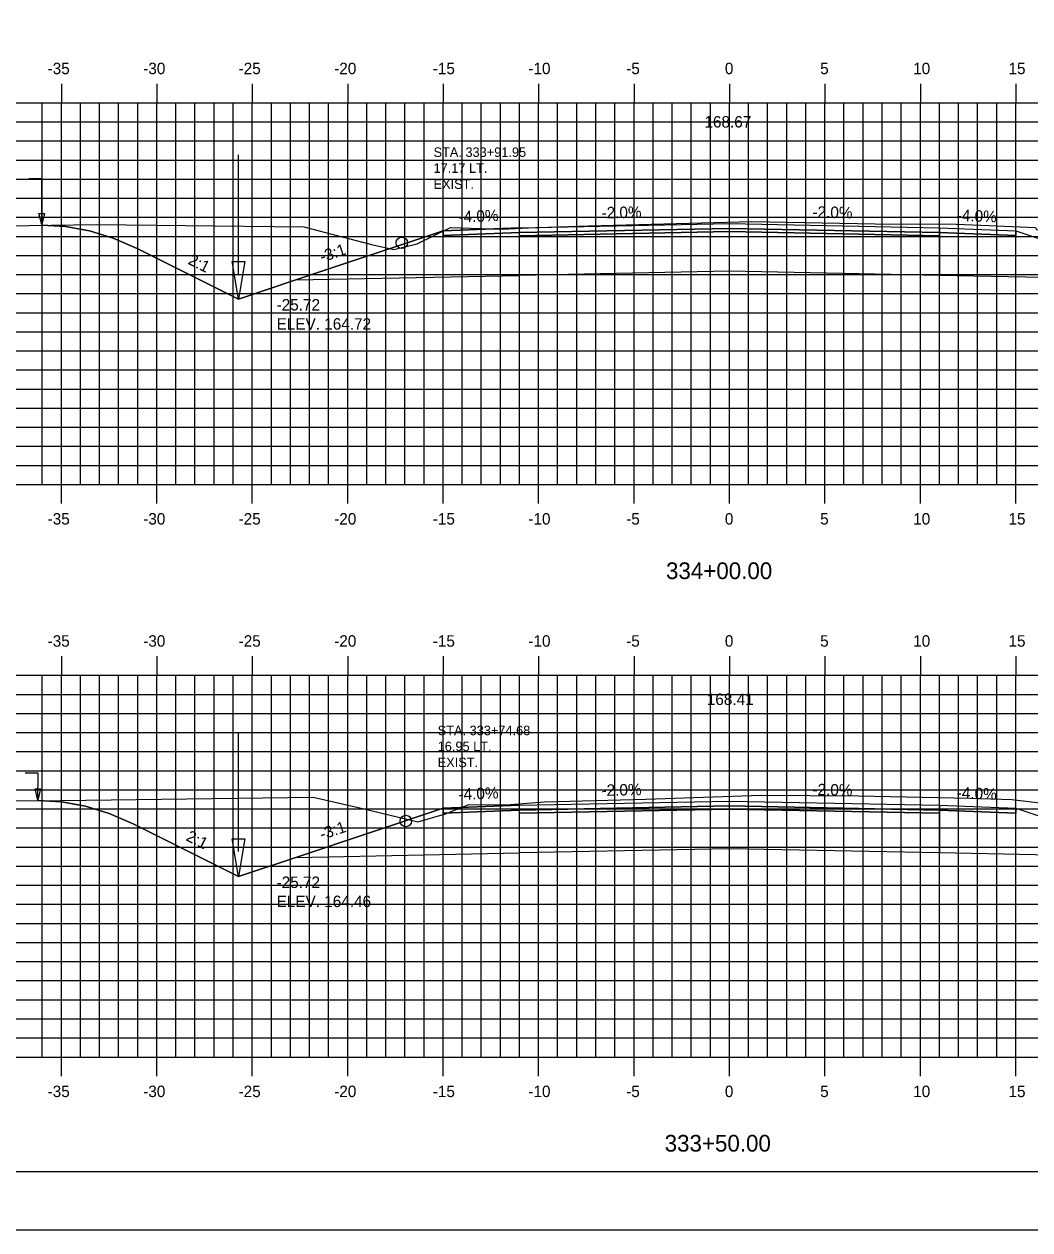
# Model space of a CAD drawing. Extents: x 1141868 to 1142038, y 608981 to 609091.
# Drawn here: x 1141913.8 to 1141966.5, y 608981.3 to 609044.5 of the extents above; entities that cross this region are included whole.
import ezdxf

# ---------------------------------------------------------------- set-up
doc = ezdxf.new("R2010")
doc.units = 0
for name, color, linetype in [('ANNOTATION', 7, 'Continuous'), ('BORDER', 7, 'Continuous'), ('D_Drainage_Ditch_Line', 7, 'Continuous'), ('D_Roadway_Centerline', 7, 'Continuous'), ('D_Roadway_Centerline_Text', 7, 'Continuous'), ('D_Roadway_Edge_Shoulder', 7, 'Continuous'), ('D_Roadway_Edge_TW', 7, 'Continuous'), ('D_Roadway_Pavement', 7, 'Continuous'), ('D_Roadway_SlopeLines', 7, 'Continuous'), ('D_Roadway_SubGrade', 7, 'Continuous'), ('D_Text_Monospaced', 7, 'Continuous'), ('D_Text_Standard', 7, 'Continuous'), ('H_V ANNOTATION', 7, 'Continuous'), ('MAJOR', 7, 'Continuous'), ('MINOR', 7, 'Continuous'), ('PLOT BOUNDARY', 7, 'Continuous'), ('S_Drainage_Invert', 7, 'Continuous'), ('S_Roadway_Centerline', 7, 'Continuous')]:
    doc.layers.add(name, color=color, linetype=linetype)

msp = doc.modelspace()

# ---------------------------------------------------------------- linework, layer by layer
for points in [[(1141914.753, 609033.917), (1141916.003, 609033.855), (1141917.253, 609033.633), (1141918.503, 609033.249), (1141919.753, 609032.704), (1141925.059, 609030.051), (1141928.059, 609031.051), (1141935.783, 609033.626), (1141935.784, 609033.626), (1141939.784, 609033.786), (1141950.784, 609034.006), (1141961.784, 609033.786), (1141965.784, 609033.626), (1141973.507, 609031.051), (1141976.507, 609030.051), (1141980.207, 609031.901), (1141981.457, 609032.44), (1141982.707, 609032.807), (1141983.957, 609033.002), (1141985.207, 609033.025)], [(1141914.544, 609003.78), (1141914.544, 609003.78), (1141915.794, 609003.711), (1141917.044, 609003.482), (1141918.294, 609003.095), (1141919.544, 609002.55), (1141925.059, 608999.792), (1141928.059, 609000.792), (1141935.783, 609003.367), (1141935.784, 609003.367), (1141939.784, 609003.527), (1141950.784, 609003.747), (1141961.784, 609003.527), (1141965.784, 609003.367), (1141973.507, 609000.792), (1141976.507, 608999.792), (1141981.022, 609002.05), (1141982.272, 609002.591), (1141983.522, 609002.965), (1141984.772, 609003.172), (1141986.022, 609003.211)]]:
    msp.add_lwpolyline(points)
at = {"layer": 'BORDER'}
msp.add_lwpolyline([(1141875.784, 608984.335), (1142035.784, 608984.335), (1142035.784, 609089.335), (1141875.784, 609089.335)], close=True, dxfattribs=at)
at = {"layer": 'D_Drainage_Ditch_Line'}
for p, q in [((1141925.059, 609031.363), (1141925.06, 609037.607)), ((1141925.059, 609001.104), (1141925.06, 609007.348))]:
    msp.add_line(p, q, dxfattribs=at)
for points in [[(1141924.731, 609032.02), (1141925.387, 609032.02), (1141925.059, 609030.051)], [(1141924.731, 609001.761), (1141925.387, 609001.761), (1141925.059, 608999.792)]]:
    msp.add_lwpolyline(points, close=True, dxfattribs=at)
at = {"layer": 'D_Roadway_Edge_Shoulder'}
for points in [[(1141939.784, 609033.786), (1141935.784, 609033.626), (1141935.784, 609033.376), (1141939.784, 609033.536)], [(1141961.784, 609033.786), (1141965.784, 609033.626), (1141965.784, 609033.376), (1141961.784, 609033.536)], [(1141939.784, 609003.527), (1141935.784, 609003.367), (1141935.784, 609003.117), (1141939.784, 609003.277)], [(1141961.784, 609003.527), (1141965.784, 609003.367), (1141965.784, 609003.117), (1141961.784, 609003.277)]]:
    msp.add_lwpolyline(points, close=True, dxfattribs=at)
at = {"layer": 'D_Roadway_Edge_TW'}
for points in [[(1141939.784, 609033.536), (1141939.784, 609033.786), (1141950.784, 609034.006), (1141961.784, 609033.786), (1141961.784, 609033.536), (1141950.784, 609033.756)], [(1141939.784, 609003.277), (1141939.784, 609003.527), (1141950.784, 609003.747), (1141961.784, 609003.527), (1141961.784, 609003.277), (1141950.784, 609003.497)]]:
    msp.add_lwpolyline(points, close=True, dxfattribs=at)
at = {"layer": 'D_Roadway_Pavement'}
for points in [[(1141939.784, 609033.369), (1141939.784, 609033.536), (1141950.784, 609033.756), (1141961.784, 609033.536), (1141961.784, 609033.369), (1141950.784, 609033.589)], [(1141939.784, 609003.11), (1141939.784, 609003.277), (1141950.784, 609003.497), (1141961.784, 609003.277), (1141961.784, 609003.11), (1141950.784, 609003.33)]]:
    msp.add_lwpolyline(points, close=True, dxfattribs=at)
at = {"layer": 'D_Roadway_SlopeLines'}
for points in [[(1141925.059, 609030.051), (1141919.753, 609032.704), (1141918.503, 609033.249), (1141917.253, 609033.633), (1141916.003, 609033.855), (1141914.753, 609033.917)], [(1141928.059, 609031.051), (1141925.059, 609030.051)], [(1141925.059, 608999.792), (1141919.544, 609002.55), (1141918.294, 609003.095), (1141917.044, 609003.482), (1141915.794, 609003.711), (1141914.544, 609003.78)], [(1141928.059, 609000.792), (1141925.059, 608999.792)]]:
    msp.add_lwpolyline(points, dxfattribs=at)
at = {"layer": 'D_Roadway_SubGrade'}
for points in [[(1141939.784, 609033.369), (1141939.784, 609033.536), (1141935.784, 609033.376), (1141935.784, 609033.626), (1141935.783, 609033.626), (1141928.059, 609031.051), (1141939.784, 609031.286)], [(1141939.784, 609031.286), (1141939.784, 609033.369), (1141950.784, 609033.589), (1141961.784, 609033.369), (1141961.784, 609031.286), (1141950.784, 609031.506)], [(1141961.784, 609033.369), (1141961.784, 609033.536), (1141965.784, 609033.376), (1141965.784, 609033.626), (1141965.784, 609033.626), (1141973.507, 609031.051), (1141961.784, 609031.286)], [(1141939.784, 609003.11), (1141939.784, 609003.277), (1141935.784, 609003.117), (1141935.784, 609003.367), (1141935.783, 609003.367), (1141928.059, 609000.792), (1141939.784, 609001.027)], [(1141939.784, 609001.027), (1141939.784, 609003.11), (1141950.784, 609003.33), (1141961.784, 609003.11), (1141961.784, 609001.027), (1141950.784, 609001.247)], [(1141961.784, 609003.11), (1141961.784, 609003.277), (1141965.784, 609003.117), (1141965.784, 609003.367), (1141965.784, 609003.367), (1141973.507, 609000.792), (1141961.784, 609001.027)]]:
    msp.add_lwpolyline(points, close=True, dxfattribs=at)
at = {"layer": 'D_Text_Standard'}
for points in [[(1141914.753, 609033.954), (1141914.76, 609036.346), (1141914.08, 609036.346)], [(1141914.544, 609003.8), (1141914.563, 609005.203), (1141913.883, 609005.203)]]:
    msp.add_lwpolyline(points, dxfattribs=at)
for points in [[(1141914.753, 609033.954), (1141914.609, 609034.537), (1141914.9, 609034.536)], [(1141914.544, 609003.8), (1141914.406, 609004.384), (1141914.697, 609004.38)]]:
    msp.add_lwpolyline(points, close=True, dxfattribs=at)
at = {"layer": 'MAJOR'}
for p, q in [((1141915.784, 609041.337), (1141915.784, 609040.335)), ((1141920.784, 609041.337), (1141920.784, 609040.335)), ((1141925.784, 609041.337), (1141925.784, 609040.335)), ((1141930.784, 609041.337), (1141930.784, 609040.335)), ((1141935.784, 609041.337), (1141935.784, 609040.335)), ((1141940.784, 609041.337), (1141940.784, 609040.335)), ((1141945.784, 609041.337), (1141945.784, 609040.335)), ((1141950.784, 609041.337), (1141950.784, 609040.335)), ((1141955.784, 609041.337), (1141955.784, 609040.335)), ((1141960.784, 609041.337), (1141960.784, 609040.335)), ((1141965.784, 609041.337), (1141965.784, 609040.335)), ((1141880.784, 609040.335), (1142020.784, 609040.335)), ((1141880.784, 609040.335), (1142020.784, 609040.335)), ((1141915.784, 609020.335), (1141915.784, 609040.335)), ((1141920.784, 609020.335), (1141920.784, 609040.335)), ((1141925.784, 609020.335), (1141925.784, 609040.335)), ((1141930.784, 609020.335), (1141930.784, 609040.335)), ((1141935.784, 609020.335), (1141935.784, 609040.335)), ((1141940.784, 609020.335), (1141940.784, 609040.335)), ((1141945.784, 609020.335), (1141945.784, 609040.335)), ((1141950.784, 609020.335), (1141950.784, 609040.335)), ((1141955.784, 609020.335), (1141955.784, 609040.335)), ((1141960.784, 609020.335), (1141960.784, 609040.335)), ((1141965.784, 609020.335), (1141965.784, 609040.335)), ((1141880.784, 609035.335), (1142020.784, 609035.335)), ((1141880.784, 609030.335), (1142020.784, 609030.335)), ((1141880.784, 609025.335), (1142020.784, 609025.335)), ((1141880.784, 609020.335), (1142020.784, 609020.335)), ((1141880.784, 609020.335), (1142020.784, 609020.335)), ((1141915.784, 609019.333), (1141915.784, 609020.335)), ((1141920.784, 609019.333), (1141920.784, 609020.335)), ((1141925.784, 609019.333), (1141925.784, 609020.335)), ((1141930.784, 609019.333), (1141930.784, 609020.335)), ((1141935.784, 609019.333), (1141935.784, 609020.335)), ((1141940.784, 609019.333), (1141940.784, 609020.335)), ((1141945.784, 609019.333), (1141945.784, 609020.335)), ((1141950.784, 609019.333), (1141950.784, 609020.335)), ((1141955.784, 609019.333), (1141955.784, 609020.335)), ((1141960.784, 609019.333), (1141960.784, 609020.335)), ((1141965.784, 609019.333), (1141965.784, 609020.335)), ((1141915.784, 609011.337), (1141915.784, 609010.335)), ((1141920.784, 609011.337), (1141920.784, 609010.335)), ((1141925.784, 609011.337), (1141925.784, 609010.335)), ((1141930.784, 609011.337), (1141930.784, 609010.335)), ((1141935.784, 609011.337), (1141935.784, 609010.335)), ((1141940.784, 609011.337), (1141940.784, 609010.335)), ((1141945.784, 609011.337), (1141945.784, 609010.335)), ((1141950.784, 609011.337), (1141950.784, 609010.335)), ((1141955.784, 609011.337), (1141955.784, 609010.335)), ((1141960.784, 609011.337), (1141960.784, 609010.335)), ((1141965.784, 609011.337), (1141965.784, 609010.335)), ((1141880.784, 609010.335), (1142020.784, 609010.335)), ((1141880.784, 609010.335), (1142020.784, 609010.335)), ((1141915.784, 608990.335), (1141915.784, 609010.335)), ((1141920.784, 608990.335), (1141920.784, 609010.335)), ((1141925.784, 608990.335), (1141925.784, 609010.335)), ((1141930.784, 608990.335), (1141930.784, 609010.335)), ((1141935.784, 608990.335), (1141935.784, 609010.335)), ((1141940.784, 608990.335), (1141940.784, 609010.335)), ((1141945.784, 608990.335), (1141945.784, 609010.335)), ((1141950.784, 608990.335), (1141950.784, 609010.335)), ((1141955.784, 608990.335), (1141955.784, 609010.335)), ((1141960.784, 608990.335), (1141960.784, 609010.335)), ((1141965.784, 608990.335), (1141965.784, 609010.335)), ((1141880.784, 609005.335), (1142020.784, 609005.335)), ((1141880.784, 609000.335), (1142020.784, 609000.335)), ((1141880.784, 608995.335), (1142020.784, 608995.335)), ((1141880.784, 608990.335), (1142020.784, 608990.335)), ((1141880.784, 608990.335), (1142020.784, 608990.335)), ((1141915.784, 608989.333), (1141915.784, 608990.335)), ((1141920.784, 608989.333), (1141920.784, 608990.335)), ((1141925.784, 608989.333), (1141925.784, 608990.335)), ((1141930.784, 608989.333), (1141930.784, 608990.335)), ((1141935.784, 608989.333), (1141935.784, 608990.335)), ((1141940.784, 608989.333), (1141940.784, 608990.335)), ((1141945.784, 608989.333), (1141945.784, 608990.335)), ((1141950.784, 608989.333), (1141950.784, 608990.335)), ((1141955.784, 608989.333), (1141955.784, 608990.335)), ((1141960.784, 608989.333), (1141960.784, 608990.335)), ((1141965.784, 608989.333), (1141965.784, 608990.335))]:
    msp.add_line(p, q, dxfattribs=at)
at = {"layer": 'MINOR'}
for p, q in [((1141914.784, 609020.335), (1141914.784, 609040.335)), ((1141916.784, 609020.335), (1141916.784, 609040.335)), ((1141917.784, 609020.335), (1141917.784, 609040.335)), ((1141918.784, 609020.335), (1141918.784, 609040.335)), ((1141919.784, 609020.335), (1141919.784, 609040.335)), ((1141921.784, 609020.335), (1141921.784, 609040.335)), ((1141922.784, 609020.335), (1141922.784, 609040.335)), ((1141923.784, 609020.335), (1141923.784, 609040.335)), ((1141924.784, 609020.335), (1141924.784, 609040.335)), ((1141926.784, 609020.335), (1141926.784, 609040.335)), ((1141927.784, 609020.335), (1141927.784, 609040.335)), ((1141928.784, 609020.335), (1141928.784, 609040.335)), ((1141929.784, 609020.335), (1141929.784, 609040.335)), ((1141931.784, 609020.335), (1141931.784, 609040.335)), ((1141932.784, 609020.335), (1141932.784, 609040.335)), ((1141933.784, 609020.335), (1141933.784, 609040.335)), ((1141934.784, 609020.335), (1141934.784, 609040.335)), ((1141936.784, 609020.335), (1141936.784, 609040.335)), ((1141937.784, 609020.335), (1141937.784, 609040.335)), ((1141938.784, 609020.335), (1141938.784, 609040.335)), ((1141939.784, 609020.335), (1141939.784, 609040.335)), ((1141941.784, 609020.335), (1141941.784, 609040.335)), ((1141942.784, 609020.335), (1141942.784, 609040.335)), ((1141943.784, 609020.335), (1141943.784, 609040.335)), ((1141944.784, 609020.335), (1141944.784, 609040.335)), ((1141946.784, 609020.335), (1141946.784, 609040.335)), ((1141947.784, 609020.335), (1141947.784, 609040.335)), ((1141948.784, 609020.335), (1141948.784, 609040.335)), ((1141949.784, 609020.335), (1141949.784, 609040.335)), ((1141951.784, 609020.335), (1141951.784, 609040.335)), ((1141952.784, 609020.335), (1141952.784, 609040.335)), ((1141953.784, 609020.335), (1141953.784, 609040.335)), ((1141954.784, 609020.335), (1141954.784, 609040.335)), ((1141956.784, 609020.335), (1141956.784, 609040.335)), ((1141957.784, 609020.335), (1141957.784, 609040.335)), ((1141958.784, 609020.335), (1141958.784, 609040.335)), ((1141959.784, 609020.335), (1141959.784, 609040.335)), ((1141961.784, 609020.335), (1141961.784, 609040.335)), ((1141962.784, 609020.335), (1141962.784, 609040.335)), ((1141963.784, 609020.335), (1141963.784, 609040.335)), ((1141964.784, 609020.335), (1141964.784, 609040.335)), ((1141880.784, 609039.335), (1142020.784, 609039.335)), ((1141880.784, 609038.335), (1142020.784, 609038.335)), ((1141880.784, 609037.335), (1142020.784, 609037.335)), ((1141880.784, 609036.335), (1142020.784, 609036.335)), ((1141880.784, 609034.335), (1142020.784, 609034.335)), ((1141880.784, 609033.335), (1142020.784, 609033.335)), ((1141880.784, 609032.335), (1142020.784, 609032.335)), ((1141880.784, 609031.335), (1142020.784, 609031.335)), ((1141880.784, 609029.335), (1142020.784, 609029.335)), ((1141880.784, 609028.335), (1142020.784, 609028.335)), ((1141880.784, 609027.335), (1142020.784, 609027.335)), ((1141880.784, 609026.335), (1142020.784, 609026.335)), ((1141880.784, 609024.335), (1142020.784, 609024.335)), ((1141880.784, 609023.335), (1142020.784, 609023.335)), ((1141880.784, 609022.335), (1142020.784, 609022.335)), ((1141880.784, 609021.335), (1142020.784, 609021.335)), ((1141914.784, 608990.335), (1141914.784, 609010.335)), ((1141916.784, 608990.335), (1141916.784, 609010.335)), ((1141917.784, 608990.335), (1141917.784, 609010.335)), ((1141918.784, 608990.335), (1141918.784, 609010.335)), ((1141919.784, 608990.335), (1141919.784, 609010.335)), ((1141921.784, 608990.335), (1141921.784, 609010.335)), ((1141922.784, 608990.335), (1141922.784, 609010.335)), ((1141923.784, 608990.335), (1141923.784, 609010.335)), ((1141924.784, 608990.335), (1141924.784, 609010.335)), ((1141926.784, 608990.335), (1141926.784, 609010.335)), ((1141927.784, 608990.335), (1141927.784, 609010.335)), ((1141928.784, 608990.335), (1141928.784, 609010.335)), ((1141929.784, 608990.335), (1141929.784, 609010.335)), ((1141931.784, 608990.335), (1141931.784, 609010.335)), ((1141932.784, 608990.335), (1141932.784, 609010.335)), ((1141933.784, 608990.335), (1141933.784, 609010.335)), ((1141934.784, 608990.335), (1141934.784, 609010.335)), ((1141936.784, 608990.335), (1141936.784, 609010.335)), ((1141937.784, 608990.335), (1141937.784, 609010.335)), ((1141938.784, 608990.335), (1141938.784, 609010.335)), ((1141939.784, 608990.335), (1141939.784, 609010.335)), ((1141941.784, 608990.335), (1141941.784, 609010.335)), ((1141942.784, 608990.335), (1141942.784, 609010.335)), ((1141943.784, 608990.335), (1141943.784, 609010.335)), ((1141944.784, 608990.335), (1141944.784, 609010.335)), ((1141946.784, 608990.335), (1141946.784, 609010.335)), ((1141947.784, 608990.335), (1141947.784, 609010.335)), ((1141948.784, 608990.335), (1141948.784, 609010.335)), ((1141949.784, 608990.335), (1141949.784, 609010.335)), ((1141951.784, 608990.335), (1141951.784, 609010.335)), ((1141952.784, 608990.335), (1141952.784, 609010.335)), ((1141953.784, 608990.335), (1141953.784, 609010.335)), ((1141954.784, 608990.335), (1141954.784, 609010.335)), ((1141956.784, 608990.335), (1141956.784, 609010.335)), ((1141957.784, 608990.335), (1141957.784, 609010.335)), ((1141958.784, 608990.335), (1141958.784, 609010.335)), ((1141959.784, 608990.335), (1141959.784, 609010.335)), ((1141961.784, 608990.335), (1141961.784, 609010.335)), ((1141962.784, 608990.335), (1141962.784, 609010.335)), ((1141963.784, 608990.335), (1141963.784, 609010.335)), ((1141964.784, 608990.335), (1141964.784, 609010.335)), ((1141880.784, 609009.335), (1142020.784, 609009.335)), ((1141880.784, 609008.335), (1142020.784, 609008.335)), ((1141880.784, 609007.335), (1142020.784, 609007.335)), ((1141880.784, 609006.335), (1142020.784, 609006.335)), ((1141880.784, 609004.335), (1142020.784, 609004.335)), ((1141880.784, 609003.335), (1142020.784, 609003.335)), ((1141880.784, 609002.335), (1142020.784, 609002.335)), ((1141880.784, 609001.335), (1142020.784, 609001.335)), ((1141880.784, 608999.335), (1142020.784, 608999.335)), ((1141880.784, 608998.335), (1142020.784, 608998.335)), ((1141880.784, 608997.335), (1142020.784, 608997.335)), ((1141880.784, 608996.335), (1142020.784, 608996.335)), ((1141880.784, 608994.335), (1142020.784, 608994.335)), ((1141880.784, 608993.335), (1142020.784, 608993.335)), ((1141880.784, 608992.335), (1142020.784, 608992.335)), ((1141880.784, 608991.335), (1142020.784, 608991.335))]:
    msp.add_line(p, q, dxfattribs=at)
at = {"layer": 'PLOT BOUNDARY'}
msp.add_lwpolyline([(1141867.691, 608981.276), (1142037.691, 608981.276), (1142037.691, 609091.276), (1141867.691, 609091.276)], close=True, dxfattribs=at)
at = {"layer": 'S_Drainage_Invert'}
for centre in [(1141933.615, 609033), (1141933.832, 609002.699)]:
    msp.add_circle(centre, 0.3, dxfattribs=at)
at = {"layer": 'S_Roadway_Centerline'}
for points in [[(1141898.714, 609033.675), (1141917.629, 609033.96), (1141928.482, 609033.842), (1141932.036, 609032.906), (1141933.204, 609032.648), (1141934.418, 609032.95), (1141936.171, 609033.793), (1141938.888, 609033.718), (1141940.258, 609033.785), (1141943.4, 609033.889), (1141951.951, 609034.107), (1141958.412, 609033.998), (1141962.656, 609033.973), (1141964.386, 609033.91), (1141966.817, 609033.803), (1141966.877, 609033.693), (1141968.111, 609033.369), (1141969.228, 609033.74), (1141970.594, 609033.351), (1141971.805, 609033.711), (1141975.428, 609033.517), (1141988.146, 609032.877), (1141997.951, 609033.132)], [(1141900.602, 609003.644), (1141901.394, 609003.749), (1141915.746, 609003.783), (1141928.977, 609003.95), (1141931.483, 609003.382), (1141934.466, 609002.656), (1141935.906, 609003.083), (1141937.139, 609003.558), (1141939.061, 609003.555), (1141941.092, 609003.71), (1141946.4, 609003.848), (1141952.444, 609004.051), (1141957.538, 609004.023), (1141963.377, 609003.905), (1141965.582, 609003.828), (1141967.5, 609003.599), (1141969.235, 609003.105), (1141970.695, 609002.835), (1141974.484, 609003.124), (1141975.978, 609003.567), (1141986.319, 609003.2), (1141995.084, 609003.033)]]:
    msp.add_lwpolyline(points, dxfattribs=at)

# ---------------------------------------------------------------- texts
at = {"layer": 'ANNOTATION'}
for s, rotation, p in [('-4.0%', 2.29061, (1141936.6, 609034.059)), ('-2.0%', 1.14576, (1141944.087, 609034.272)), ('-2.0%', 358.85424, (1141955.127, 609034.319)), ('-4.0%', 357.70939, (1141962.68, 609034.151)), ('-3:1', 18.43482, (1141929.438, 609031.965)), ('2:1', 333.43495, (1141922.373, 609031.912)), ('-4.0%', 2.29061, (1141936.6, 609003.8)), ('-2.0%', 1.14576, (1141944.087, 609004.013)), ('-2.0%', 358.85424, (1141955.127, 609004.06)), ('-4.0%', 357.70939, (1141962.68, 609003.892)), ('-3:1', 18.43482, (1141929.438, 609001.706)), ('2:1', 333.43495, (1141922.269, 609001.705))]:
    msp.add_text(s, height=0.6, rotation=rotation, dxfattribs=at).set_placement(p)
at = {"layer": 'D_Roadway_Centerline'}
for s, p in [('C', (1141950.779, 609034.006)), ('L', (1141950.784, 609033.998)), ('C', (1141950.779, 609003.747)), ('L', (1141950.784, 609003.739))]:
    msp.add_text(s, height=0.0146, dxfattribs=at).set_placement(p)
at = {"layer": 'D_Roadway_Centerline_Text'}
for s, p in [('168.67', (1141949.473, 609039.038)), ('168.41', (1141949.596, 609008.779))]:
    msp.add_text(s, height=0.6, dxfattribs=at).set_placement(p)
at = {"layer": 'D_Text_Monospaced'}
for s, height, p in [('STA. 333+91.95', 0.49998, (1141935.281, 609037.498)), ('17.17 LT.', 0.5, (1141935.281, 609036.664)), ('EXIST. ', 0.5, (1141935.281, 609035.824)), ('STA. 333+74.68', 0.49998, (1141935.499, 609007.197)), ('16.95 LT.', 0.5, (1141935.499, 609006.363)), ('EXIST. ', 0.5, (1141935.499, 609005.523))]:
    msp.add_text(s, height=height, dxfattribs=at).set_placement(p)
at = {"layer": 'D_Text_Standard'}
for s, p in [('-25.72', (1141927.059, 609029.451)), ('ELEV. 164.72', (1141927.059, 609028.449)), ('-25.72', (1141927.059, 608999.192)), ('ELEV. 164.46', (1141927.059, 608998.19))]:
    msp.add_text(s, height=0.6, dxfattribs=at).set_placement(p)
at = {"layer": 'H_V ANNOTATION'}
for s, height, p in [('-35', 0.6, (1141915.064, 609041.835)), ('-30', 0.6, (1141920.072, 609041.835)), ('-25', 0.6, (1141925.069, 609041.835)), ('-20', 0.6, (1141930.077, 609041.835)), ('-15', 0.6, (1141935.241, 609041.835)), ('-10', 0.6, (1141940.249, 609041.835)), ('-5', 0.6, (1141945.374, 609041.835)), ('0', 0.6, (1141950.543, 609041.835)), ('5', 0.6, (1141955.535, 609041.835)), ('10', 0.6, (1141960.409, 609041.835)), ('15', 0.6, (1141965.401, 609041.835)), ('-35', 0.6, (1141915.064, 609018.235)), ('-30', 0.6, (1141920.072, 609018.235)), ('-25', 0.6, (1141925.069, 609018.235)), ('-20', 0.6, (1141930.077, 609018.235)), ('-15', 0.6, (1141935.241, 609018.235)), ('-10', 0.6, (1141940.249, 609018.235)), ('-5', 0.6, (1141945.374, 609018.235)), ('0', 0.6, (1141950.543, 609018.235)), ('5', 0.6, (1141955.535, 609018.235)), ('10', 0.6, (1141960.409, 609018.235)), ('15', 0.6, (1141965.401, 609018.235)), ('334+00.00', 0.875, (1141947.46, 609015.378)), ('-35', 0.6, (1141915.064, 609011.835)), ('-30', 0.6, (1141920.072, 609011.835)), ('-25', 0.6, (1141925.069, 609011.835)), ('-20', 0.6, (1141930.077, 609011.835)), ('-15', 0.6, (1141935.241, 609011.835)), ('-10', 0.6, (1141940.249, 609011.835)), ('-5', 0.6, (1141945.374, 609011.835)), ('0', 0.6, (1141950.543, 609011.835)), ('5', 0.6, (1141955.535, 609011.835)), ('10', 0.6, (1141960.409, 609011.835)), ('15', 0.6, (1141965.401, 609011.835)), ('-35', 0.6, (1141915.064, 608988.235)), ('-30', 0.6, (1141920.072, 608988.235)), ('-25', 0.6, (1141925.069, 608988.235)), ('-20', 0.6, (1141930.077, 608988.235)), ('-15', 0.6, (1141935.241, 608988.235)), ('-10', 0.6, (1141940.249, 608988.235)), ('-5', 0.6, (1141945.374, 608988.235)), ('0', 0.6, (1141950.543, 608988.235)), ('5', 0.6, (1141955.535, 608988.235)), ('10', 0.6, (1141960.409, 608988.235)), ('15', 0.6, (1141965.401, 608988.235)), ('333+50.00', 0.875, (1141947.389, 608985.378))]:
    msp.add_text(s, height=height, dxfattribs=at).set_placement(p)
at = {"layer": 'S_Roadway_Centerline'}
for s, p in [('C', (1141951.946, 609034.107)), ('L', (1141951.951, 609034.1)), ('C', (1141952.438, 609004.051)), ('L', (1141952.444, 609004.044))]:
    msp.add_text(s, height=0.0146, dxfattribs=at).set_placement(p)

doc.saveas('drawing.dxf')
